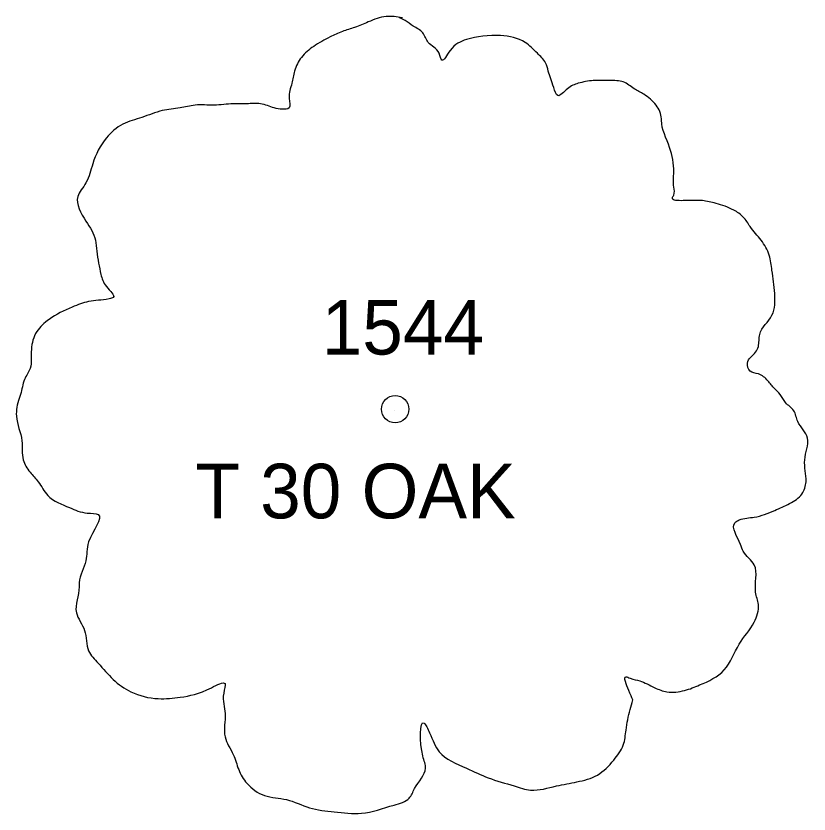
# Model space of a CAD drawing. Extents: x 1964982 to 1970452, y 1116335 to 1119906.
# Drawn here: x 1966511.04 to 1966525.57, y 1117448.46 to 1117463.08 of the extents above; entities that cross this region are included whole.
import ezdxf

# ---------------------------------------------------------------- set-up
doc = ezdxf.new("R2010")
doc.units = 0
doc.layers.add('RD_EX_VEG', color=7, linetype='Continuous')
doc.layers.add('RD_EX_VEG_txCode', color=7, linetype='Continuous')

msp = doc.modelspace()

# ---------------------------------------------------------------- linework, layer by layer
at = {"layer": 'RD_EX_VEG'}
for centre, radius in [((1966517.984, 1117455.877), 0.25), ((1966517.984, 1117455.877), 0.25), ((1966517.971, 1117455.858), 0.0001), ((1966517.971, 1117455.858), 0.0001)]:
    msp.add_circle(centre, radius, dxfattribs=at)
for points in [[(1966518.116, 1117463.044), (1966517.816, 1117463.069), (1966517.491, 1117462.969), (1966517.241, 1117462.869), (1966517.016, 1117462.794), (1966516.791, 1117462.694), (1966516.491, 1117462.52), (1966516.266, 1117462.32), (1966516.141, 1117462.07), (1966516.091, 1117461.845), (1966516.041, 1117461.57), (1966516.041, 1117461.395), (1966515.917, 1117461.37), (1966515.767, 1117461.395), (1966515.517, 1117461.47), (1966515.267, 1117461.47), (1966515.017, 1117461.47), (1966514.667, 1117461.445), (1966514.317, 1117461.445), (1966514.042, 1117461.395), (1966513.717, 1117461.345), (1966513.343, 1117461.22), (1966512.993, 1117461.095), (1966512.693, 1117460.845), (1966512.443, 1117460.371), (1966512.318, 1117460.021), (1966512.168, 1117459.771), (1966512.318, 1117459.321), (1966512.493, 1117458.971), (1966512.518, 1117458.771), (1966512.593, 1117458.346), (1966512.693, 1117458.122), (1966512.818, 1117457.922), (1966512.743, 1117457.897), (1966512.368, 1117457.847), (1966512.068, 1117457.747), (1966511.643, 1117457.522), (1966511.418, 1117457.297), (1966511.318, 1117456.972), (1966511.294, 1117456.622), (1966511.194, 1117456.422), (1966511.119, 1117456.147), (1966511.094, 1117456.072), (1966511.044, 1117455.748), (1966511.144, 1117455.298), (1966511.169, 1117454.948), (1966511.294, 1117454.723), (1966511.443, 1117454.548), (1966511.618, 1117454.298), (1966512.018, 1117454.073), (1966512.343, 1117453.973), (1966512.543, 1117453.948), (1966512.368, 1117453.449), (1966512.318, 1117453.099), (1966512.193, 1117452.699), (1966512.193, 1117452.624), (1966512.143, 1117452.149), (1966512.293, 1117451.824), (1966512.368, 1117451.449), (1966512.543, 1117451.225), (1966512.818, 1117450.925), (1966513.143, 1117450.7), (1966513.643, 1117450.575), (1966514.042, 1117450.6), (1966514.617, 1117450.775), (1966514.867, 1117450.85), (1966514.842, 1117450.675), (1966514.867, 1117450.3), (1966514.867, 1117449.875), (1966515.017, 1117449.55), (1966515.117, 1117449.275), (1966515.267, 1117449.025), (1966515.592, 1117448.801), (1966515.991, 1117448.726), (1966516.416, 1117448.576), (1966516.866, 1117448.501), (1966517.366, 1117448.476), (1966517.966, 1117448.626), (1966518.24, 1117448.751), (1966518.34, 1117448.926), (1966518.54, 1117449.3), (1966518.49, 1117449.525), (1966518.515, 1117450.125), (1966518.615, 1117449.95), (1966518.79, 1117449.6), (1966519.29, 1117449.3), (1966519.69, 1117449.125), (1966520.165, 1117448.975), (1966520.465, 1117448.901), (1966520.939, 1117448.975), (1966521.314, 1117449.05), (1966521.689, 1117449.175), (1966521.989, 1117449.45), (1966522.164, 1117449.725), (1966522.214, 1117450), (1966522.289, 1117450.375), (1966522.339, 1117450.55)], [(1966518.116, 1117463.044), (1966517.816, 1117463.069), (1966517.491, 1117462.969), (1966517.241, 1117462.869), (1966517.016, 1117462.794), (1966516.791, 1117462.694), (1966516.491, 1117462.52), (1966516.266, 1117462.32), (1966516.141, 1117462.07), (1966516.091, 1117461.845), (1966516.041, 1117461.57), (1966516.041, 1117461.395), (1966515.917, 1117461.37), (1966515.767, 1117461.395), (1966515.517, 1117461.47), (1966515.267, 1117461.47), (1966515.017, 1117461.47), (1966514.667, 1117461.445), (1966514.317, 1117461.445), (1966514.042, 1117461.395), (1966513.717, 1117461.345), (1966513.343, 1117461.22), (1966512.993, 1117461.095), (1966512.693, 1117460.845), (1966512.443, 1117460.371), (1966512.318, 1117460.021), (1966512.168, 1117459.771), (1966512.318, 1117459.321), (1966512.493, 1117458.971), (1966512.518, 1117458.771), (1966512.593, 1117458.346), (1966512.693, 1117458.122), (1966512.818, 1117457.922), (1966512.743, 1117457.897), (1966512.368, 1117457.847), (1966512.068, 1117457.747), (1966511.643, 1117457.522), (1966511.418, 1117457.297), (1966511.318, 1117456.972), (1966511.294, 1117456.622), (1966511.194, 1117456.422), (1966511.119, 1117456.147), (1966511.094, 1117456.072), (1966511.044, 1117455.748), (1966511.144, 1117455.298), (1966511.169, 1117454.948), (1966511.294, 1117454.723), (1966511.443, 1117454.548), (1966511.618, 1117454.298), (1966512.018, 1117454.073), (1966512.343, 1117453.973), (1966512.543, 1117453.948), (1966512.368, 1117453.449), (1966512.318, 1117453.099), (1966512.193, 1117452.699), (1966512.193, 1117452.624), (1966512.143, 1117452.149), (1966512.293, 1117451.824), (1966512.368, 1117451.449), (1966512.543, 1117451.225), (1966512.818, 1117450.925), (1966513.143, 1117450.7), (1966513.643, 1117450.575), (1966514.042, 1117450.6), (1966514.617, 1117450.775), (1966514.867, 1117450.85), (1966514.842, 1117450.675), (1966514.867, 1117450.3), (1966514.867, 1117449.875), (1966515.017, 1117449.55), (1966515.117, 1117449.275), (1966515.267, 1117449.025), (1966515.592, 1117448.801), (1966515.991, 1117448.726), (1966516.416, 1117448.576), (1966516.866, 1117448.501), (1966517.366, 1117448.476), (1966517.966, 1117448.626), (1966518.24, 1117448.751), (1966518.34, 1117448.926), (1966518.54, 1117449.3), (1966518.49, 1117449.525), (1966518.515, 1117450.125), (1966518.615, 1117449.95), (1966518.79, 1117449.6), (1966519.29, 1117449.3), (1966519.69, 1117449.125), (1966520.165, 1117448.975), (1966520.465, 1117448.901), (1966520.939, 1117448.975), (1966521.314, 1117449.05), (1966521.689, 1117449.175), (1966521.989, 1117449.45), (1966522.164, 1117449.725), (1966522.214, 1117450), (1966522.289, 1117450.375), (1966522.339, 1117450.55)], [(1966522.339, 1117450.55), (1966522.264, 1117450.725), (1966522.214, 1117450.975), (1966522.289, 1117450.95), (1966522.464, 1117450.9), (1966522.739, 1117450.775), (1966522.963, 1117450.7), (1966523.288, 1117450.725), (1966523.563, 1117450.825), (1966524.013, 1117451.1), (1966524.288, 1117451.574), (1966524.563, 1117451.974), (1966524.638, 1117452.299), (1966524.588, 1117452.524), (1966524.563, 1117453.024), (1966524.363, 1117453.274), (1966524.313, 1117453.399), (1966524.213, 1117453.798), (1966524.288, 1117453.848), (1966524.563, 1117453.898), (1966524.938, 1117454.023), (1966525.212, 1117454.148), (1966525.437, 1117454.323), (1966525.512, 1117454.548), (1966525.487, 1117454.948), (1966525.537, 1117455.348), (1966525.462, 1117455.498), (1966525.362, 1117455.648), (1966525.287, 1117455.848), (1966525.137, 1117455.997), (1966525.038, 1117456.147), (1966524.938, 1117456.247), (1966524.813, 1117456.397), (1966524.638, 1117456.522), (1966524.488, 1117456.572), (1966524.438, 1117456.722), (1966524.588, 1117456.922), (1966524.638, 1117457.022), (1966524.663, 1117457.247), (1966524.888, 1117457.597), (1966524.938, 1117457.997), (1966524.888, 1117458.421), (1966524.838, 1117458.696), (1966524.688, 1117458.971), (1966524.488, 1117459.221), (1966524.363, 1117459.396), (1966524.188, 1117459.521), (1966523.863, 1117459.646), (1966523.613, 1117459.696), (1966523.263, 1117459.696), (1966523.063, 1117459.746), (1966523.088, 1117459.796), (1966523.088, 1117459.946), (1966523.088, 1117460.221), (1966523.013, 1117460.67), (1966522.863, 1117461.17), (1966522.863, 1117461.195), (1966522.763, 1117461.445), (1966522.539, 1117461.645), (1966522.364, 1117461.745), (1966522.164, 1117461.87), (1966521.914, 1117461.895), (1966521.614, 1117461.895), (1966521.339, 1117461.845), (1966521.139, 1117461.745), (1966520.964, 1117461.62), (1966520.889, 1117461.77), (1966520.789, 1117462.07), (1966520.739, 1117462.22), (1966520.589, 1117462.395), (1966520.365, 1117462.595), (1966519.915, 1117462.719), (1966519.29, 1117462.645), (1966518.99, 1117462.445), (1966518.84, 1117462.27), (1966518.79, 1117462.395), (1966518.59, 1117462.595), (1966518.49, 1117462.769), (1966518.315, 1117462.894), (1966518.166, 1117462.994), (1966518.066, 1117463.044)], [(1966522.339, 1117450.55), (1966522.264, 1117450.725), (1966522.214, 1117450.975), (1966522.289, 1117450.95), (1966522.464, 1117450.9), (1966522.739, 1117450.775), (1966522.963, 1117450.7), (1966523.288, 1117450.725), (1966523.563, 1117450.825), (1966524.013, 1117451.1), (1966524.288, 1117451.574), (1966524.563, 1117451.974), (1966524.638, 1117452.299), (1966524.588, 1117452.524), (1966524.563, 1117453.024), (1966524.363, 1117453.274), (1966524.313, 1117453.399), (1966524.213, 1117453.798), (1966524.288, 1117453.848), (1966524.563, 1117453.898), (1966524.938, 1117454.023), (1966525.212, 1117454.148), (1966525.437, 1117454.323), (1966525.512, 1117454.548), (1966525.487, 1117454.948), (1966525.537, 1117455.348), (1966525.462, 1117455.498), (1966525.362, 1117455.648), (1966525.287, 1117455.848), (1966525.137, 1117455.997), (1966525.038, 1117456.147), (1966524.938, 1117456.247), (1966524.813, 1117456.397), (1966524.638, 1117456.522), (1966524.488, 1117456.572), (1966524.438, 1117456.722), (1966524.588, 1117456.922), (1966524.638, 1117457.022), (1966524.663, 1117457.247), (1966524.888, 1117457.597), (1966524.938, 1117457.997), (1966524.888, 1117458.421), (1966524.838, 1117458.696), (1966524.688, 1117458.971), (1966524.488, 1117459.221), (1966524.363, 1117459.396), (1966524.188, 1117459.521), (1966523.863, 1117459.646), (1966523.613, 1117459.696), (1966523.263, 1117459.696), (1966523.063, 1117459.746), (1966523.088, 1117459.796), (1966523.088, 1117459.946), (1966523.088, 1117460.221), (1966523.013, 1117460.67), (1966522.863, 1117461.17), (1966522.863, 1117461.195), (1966522.763, 1117461.445), (1966522.539, 1117461.645), (1966522.364, 1117461.745), (1966522.164, 1117461.87), (1966521.914, 1117461.895), (1966521.614, 1117461.895), (1966521.339, 1117461.845), (1966521.139, 1117461.745), (1966520.964, 1117461.62), (1966520.889, 1117461.77), (1966520.789, 1117462.07), (1966520.739, 1117462.22), (1966520.589, 1117462.395), (1966520.365, 1117462.595), (1966519.915, 1117462.719), (1966519.29, 1117462.645), (1966518.99, 1117462.445), (1966518.84, 1117462.27), (1966518.79, 1117462.395), (1966518.59, 1117462.595), (1966518.49, 1117462.769), (1966518.315, 1117462.894), (1966518.166, 1117462.994), (1966518.066, 1117463.044)]]:
    msp.add_spline(points, degree=3, dxfattribs=at)

# ---------------------------------------------------------------- texts
at = {"layer": 'RD_EX_VEG_txCode'}
for s, p in [('1544', (1966516.637, 1117456.877)), ('1544', (1966516.637, 1117456.877)), ('T 30 OAK', (1966514.322, 1117453.877)), ('T 30 OAK', (1966514.322, 1117453.877))]:
    msp.add_text(s, height=1, dxfattribs=at).set_placement(p)

doc.saveas('drawing.dxf')
